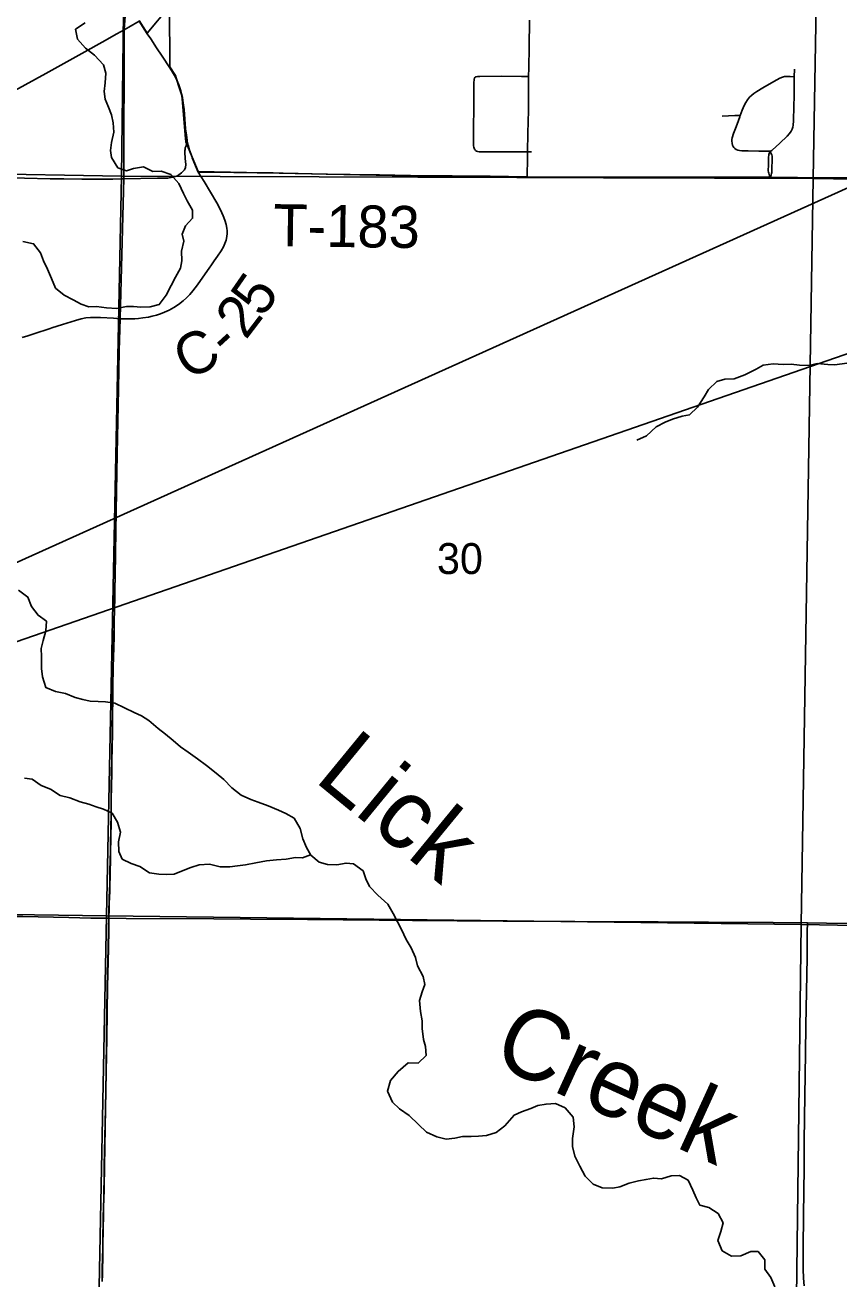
# Model space of a CAD drawing. Extents: x 0 to 34, y 0 to 22.
# Drawn here: x 5.615 to 6.718, y 15.064 to 16.761 of the extents above; entities that cross this region are included whole.
import ezdxf

# ---------------------------------------------------------------- set-up
doc = ezdxf.new("R2010")
doc.units = 0
for name, color, linetype in [('GM_X_City_Street', 7, 'Continuous'), ('GM_X_Corporation', 7, 'Continuous'), ('GM_X_County_Road', 7, 'Continuous'), ('GM_X_County_Road_Text', 7, 'Continuous'), ('GM_X_Minor_River', 7, 'Continuous'), ('GM_X_Minor_River_Text', 7, 'Continuous'), ('GM_X_Section_Text', 7, 'Continuous'), ('GM_X_State_Route', 7, 'Continuous'), ('GM_X_Township_Road', 7, 'Continuous'), ('GM_X_Township_Road_Text', 7, 'Continuous'), ('GM_X_US_Route', 7, 'Continuous'), ('SH_Data', 7, 'Continuous')]:
    doc.layers.add(name, color=color, linetype=linetype)

msp = doc.modelspace()

# ---------------------------------------------------------------- linework, layer by layer
at = {"layer": 'GM_X_City_Street'}
for points in [[(6.2953, 16.5557), (6.2955, 16.5629), (6.2958, 16.5747), (6.296, 16.5897), (6.2964, 16.6151), (6.2971, 16.6456), (6.2972, 16.6773), (6.2974, 16.6915), (6.2976, 16.7034), (6.298, 16.7314), (6.2986, 16.768)], [(6.6245, 16.5907), (6.6259, 16.5911), (6.6268, 16.5914), (6.6275, 16.5918), (6.6376, 16.6016), (6.6474, 16.6111), (6.6507, 16.6147), (6.6529, 16.6177), (6.6543, 16.6203), (6.6553, 16.623), (6.6558, 16.626), (6.6562, 16.6315), (6.6567, 16.6513), (6.657, 16.665), (6.6573, 16.6913), (6.6574, 16.7017)], [(6.2267, 16.5907), (6.2257, 16.5915), (6.2249, 16.5925), (6.2242, 16.5934), (6.2237, 16.5945), (6.2232, 16.5958), (6.2229, 16.598), (6.2226, 16.6027), (6.2227, 16.6189), (6.2233, 16.6524), (6.2232, 16.6691), (6.2233, 16.6834), (6.2236, 16.6872), (6.2237, 16.6883), (6.224, 16.6889), (6.2242, 16.6895), (6.2248, 16.6903), (6.2255, 16.691)], [(6.2255, 16.691), (6.2266, 16.6913), (6.2282, 16.6916), (6.2292, 16.6917), (6.23, 16.6917), (6.2315, 16.6918), (6.2609, 16.6922), (6.2876, 16.6917), (6.2974, 16.6915)], [(6.6245, 16.5907), (6.6167, 16.5907), (6.6092, 16.5908), (6.5948, 16.5909), (6.5861, 16.5909), (6.5832, 16.5913), (6.5809, 16.5919), (6.5787, 16.5928), (6.5768, 16.5941), (6.5752, 16.5957), (6.5743, 16.5971), (6.5736, 16.5987), (6.573, 16.601), (6.5726, 16.6045), (6.5726, 16.6062), (6.5731, 16.6086), (6.575, 16.6145), (6.5785, 16.6237), (6.5816, 16.6319), (6.5835, 16.6373), (6.5841, 16.6389), (6.5867, 16.646), (6.5894, 16.6522), (6.5917, 16.6566), (6.5941, 16.6601), (6.5967, 16.6635), (6.5997, 16.6665), (6.6025, 16.6688), (6.6066, 16.6715), (6.6147, 16.6762), (6.6297, 16.685), (6.6378, 16.6895), (6.6411, 16.6909), (6.644, 16.6916), (6.6469, 16.6918), (6.6518, 16.6916), (6.6573, 16.6913)], [(6.5598, 16.638), (6.5769, 16.6387), (6.5841, 16.6389)], [(6.2267, 16.5907), (6.2286, 16.5901), (6.2307, 16.5896), (6.2325, 16.5895), (6.2597, 16.5895), (6.2901, 16.5895), (6.296, 16.5897), (6.3013, 16.5899)], [(6.6248, 16.5547), (6.6239, 16.5572), (6.6232, 16.5591), (6.6227, 16.5609), (6.6223, 16.5624), (6.6221, 16.5641), (6.6222, 16.5719), (6.6223, 16.5811), (6.6224, 16.5829), (6.6227, 16.5847), (6.623, 16.5861), (6.6245, 16.5907)], [(6.6248, 16.5547), (6.626, 16.5585), (6.6265, 16.5602), (6.6268, 16.5616), (6.627, 16.5636), (6.6274, 16.5827), (6.6272, 16.584), (6.6267, 16.5858), (6.6261, 16.5872), (6.6245, 16.5907)]]:
    msp.add_lwpolyline(points, dxfattribs=at)
at = {"layer": 'GM_X_Corporation'}
for points in [[(5.7585, 17.5867), (6.7004, 17.5689), (6.6829, 16.5538), (5.7459, 16.557), (5.7581, 17.5537)], [(4.7439, 17.5807), (5.7581, 17.5537), (5.7459, 16.557), (4.7141, 16.575)], [(6.7004, 17.5689), (7.7016, 17.5373), (7.6999, 16.5369), (6.6829, 16.5538)], [(4.7141, 16.575), (5.7459, 16.557), (5.726, 15.5556), (4.7157, 15.5696)], [(5.7459, 16.557), (6.6829, 16.5538), (6.6666, 15.5439), (5.726, 15.5556)], [(6.6829, 16.5538), (7.6999, 16.5369), (7.6779, 15.5253), (6.6666, 15.5439)], [(4.7157, 15.5696), (5.726, 15.5556), (5.7061, 14.5519), (4.7065, 14.5692)], [(5.726, 15.5556), (6.6666, 15.5439), (6.6541, 14.5346), (6.6355, 14.5349), (5.7061, 14.5519)]]:
    msp.add_lwpolyline(points, close=True, dxfattribs=at)
for points in [[(5.7198, 15.0614), (5.72, 15.0701), (5.7201, 15.0788), (5.7203, 15.0919), (5.7206, 15.1062), (5.7207, 15.1149), (5.721, 15.1273), (5.7212, 15.136), (5.7214, 15.1478), (5.7217, 15.1615), (5.722, 15.1739), (5.7222, 15.1851), (5.7224, 15.1969), (5.7226, 15.2087), (5.7228, 15.2174), (5.7243, 15.2951), (5.7251, 15.3448), (5.726, 15.3908), (5.7269, 15.4604), (5.7281, 15.5114), (5.7285, 15.5381), (5.7288, 15.553), (5.7291, 15.566), (5.7293, 15.5735), (5.7296, 15.5809), (5.7298, 15.5896), (5.7301, 15.5989), (5.7303, 15.6083), (5.7305, 15.6176), (5.7307, 15.63), (5.731, 15.6443), (5.7313, 15.6586), (5.7315, 15.6673), (5.7317, 15.6784), (5.7319, 15.6896), (5.7319, 15.6971), (5.732, 15.7095), (5.732, 15.7176), (5.7322, 15.7269), (5.7323, 15.7325), (5.7326, 15.748), (5.7329, 15.7667), (5.7332, 15.7828), (5.7335, 15.7958), (5.7336, 15.8107), (5.7338, 15.8306), (5.734, 15.8468), (5.7342, 15.866), (5.7348, 15.8946), (5.7351, 15.9052), (5.7354, 15.9207), (5.7357, 15.9325), (5.7361, 15.9524), (5.7365, 15.9721), (5.7367, 15.9847), (5.7369, 15.9995), (5.7373, 16.0151), (5.7376, 16.0481), (5.7388, 16.104), (5.74, 16.1817), (5.7418, 16.2693), (5.7428, 16.3209), (5.7441, 16.3641), (5.7491, 16.5539), (5.7495, 16.7555), (5.7536, 16.8097)], [(5.7536, 16.8097), (5.7495, 16.7555), (5.7491, 16.5539), (5.7441, 16.3641), (5.7428, 16.3209), (5.7418, 16.2693), (5.74, 16.1817), (5.7388, 16.104), (5.7376, 16.0481), (5.7373, 16.0151), (5.7369, 15.9995), (5.7367, 15.9847), (5.7365, 15.9721), (5.7361, 15.9524), (5.7357, 15.9325), (5.7354, 15.9207), (5.7351, 15.9052), (5.7348, 15.8946), (5.7342, 15.866), (5.734, 15.8468), (5.7338, 15.8306), (5.7336, 15.8107), (5.7335, 15.7958), (5.7332, 15.7828), (5.7329, 15.7667), (5.7326, 15.748), (5.7323, 15.7325), (5.7322, 15.7269), (5.732, 15.7176), (5.732, 15.7095), (5.7319, 15.6971), (5.7319, 15.6896), (5.7317, 15.6784), (5.7315, 15.6673), (5.7313, 15.6586), (5.731, 15.6443), (5.7307, 15.63), (5.7305, 15.6176), (5.7303, 15.6083), (5.7301, 15.5989), (5.7298, 15.5896), (5.7296, 15.5809), (5.7293, 15.5735), (5.7291, 15.566), (5.7288, 15.553), (5.7285, 15.5381), (5.7281, 15.5114), (5.7269, 15.4604), (5.726, 15.3908), (5.7251, 15.3448), (5.7243, 15.2951), (5.7228, 15.2174), (5.7226, 15.2087), (5.7224, 15.1969), (5.7222, 15.1851), (5.722, 15.1739), (5.7217, 15.1615), (5.7214, 15.1478), (5.7212, 15.136), (5.721, 15.1273), (5.7207, 15.1149), (5.7206, 15.1062), (5.7203, 15.0919), (5.7201, 15.0788), (5.72, 15.0701), (5.7198, 15.0614)], [(5.7701, 16.7674), (5.7809, 16.7504), (5.811, 16.7863), (5.8114, 16.7046), (5.8192, 16.693), (5.823, 16.681), (5.8279, 16.666), (5.8287, 16.6567), (5.8324, 16.6128), (5.8332, 16.6034), (5.8419, 16.5823), (5.8501, 16.5633), (6.1563, 16.5568), (6.1872, 16.5561), (6.2206, 16.5561), (6.2673, 16.556), (6.2953, 16.556), (6.3807, 16.5555), (6.5852, 16.5555), (6.6248, 16.5554), (6.8105, 16.5532)]]:
    msp.add_lwpolyline(points, dxfattribs=at)
at = {"layer": 'GM_X_County_Road'}
msp.add_line((5.8579, 16.5496), (5.8501, 16.5624), dxfattribs=at)
for points in [[(5.7497, 16.7549), (5.756, 16.7585), (5.77, 16.7666)], [(5.7809, 16.7494), (5.7768, 16.7556), (5.7722, 16.7629), (5.77, 16.7666)], [(5.4185, 16.5607), (5.4228, 16.5647), (5.4314, 16.5719), (5.4411, 16.5796), (5.4506, 16.5865), (5.4604, 16.5931), (5.473, 16.601), (5.4923, 16.6122), (5.5216, 16.6286), (5.6017, 16.6726), (5.6436, 16.6958), (5.6963, 16.725), (5.7198, 16.738), (5.7398, 16.7492), (5.7497, 16.7549)], [(5.8114, 16.7036), (5.8013, 16.7193), (5.7937, 16.7306), (5.7859, 16.7425), (5.7809, 16.7494)], [(5.8352, 16.6041), (5.835, 16.6053), (5.8339, 16.6121), (5.8329, 16.6208), (5.8308, 16.6468), (5.8297, 16.6561), (5.8285, 16.6634), (5.8274, 16.6682), (5.8263, 16.6723), (5.8236, 16.6805), (5.8216, 16.6856), (5.8192, 16.6906), (5.8166, 16.6955), (5.8114, 16.7036)], [(5.833, 16.5725), (5.8326, 16.5768), (5.8324, 16.5806), (5.832, 16.5892), (5.832, 16.5914), (5.8322, 16.593), (5.8325, 16.5949), (5.833, 16.5971), (5.8352, 16.6041)], [(5.8501, 16.5624), (5.8442, 16.576), (5.842, 16.5816), (5.8416, 16.5825), (5.8384, 16.592), (5.8365, 16.5986), (5.8352, 16.6041)], [(5.7493, 16.5533), (5.7947, 16.554), (5.8085, 16.5539), (5.8158, 16.5552), (5.8219, 16.5572), (5.8274, 16.5612), (5.8313, 16.5652), (5.8326, 16.5686), (5.833, 16.5725)], [(5.4185, 16.5607), (5.4269, 16.5601), (5.434, 16.5598), (5.4521, 16.5591), (5.4657, 16.5587), (5.4777, 16.5583), (5.4962, 16.5578), (5.5156, 16.557), (5.5514, 16.5558), (5.5725, 16.5553), (5.5937, 16.5547), (5.6148, 16.5541), (5.6496, 16.5532), (5.6682, 16.553), (5.6924, 16.5527), (5.7136, 16.5527), (5.7344, 16.5529), (5.7459, 16.5531), (5.7477, 16.5532), (5.7493, 16.5533)], [(5.7443, 16.3635), (5.7587, 16.3637), (5.7641, 16.3639), (5.7693, 16.3642), (5.7751, 16.365), (5.7826, 16.3661), (5.7876, 16.3671), (5.7935, 16.3686), (5.7988, 16.3703), (5.8045, 16.3725), (5.8106, 16.3754), (5.8171, 16.379), (5.8232, 16.3832), (5.8296, 16.388), (5.8342, 16.392), (5.8385, 16.3964), (5.8429, 16.4015), (5.8492, 16.4099), (5.8564, 16.42), (5.865, 16.4323), (5.8682, 16.4369), (5.8717, 16.442), (5.8763, 16.4486), (5.881, 16.4558), (5.8841, 16.4612), (5.8861, 16.4656), (5.8877, 16.4702), (5.8887, 16.4749), (5.8892, 16.4792), (5.8892, 16.4828), (5.8889, 16.4864), (5.888, 16.4912), (5.8862, 16.497), (5.8837, 16.5033), (5.8801, 16.5112), (5.8752, 16.5205), (5.8668, 16.535), (5.8579, 16.5496)], [(5.7443, 16.3635), (5.7351, 16.3644), (5.7177, 16.3655), (5.7108, 16.3657), (5.7039, 16.3655), (5.6976, 16.3649), (5.6915, 16.3638), (5.6836, 16.3616), (5.6664, 16.3561), (5.6516, 16.3513), (5.6493, 16.3505), (5.6274, 16.3434), (5.6191, 16.3408), (5.6114, 16.3383)], [(5.735, 15.892), (5.735, 15.8941), (5.7353, 15.9046), (5.7356, 15.9202), (5.736, 15.932), (5.7363, 15.9518), (5.7367, 15.9716), (5.7369, 15.9842), (5.7372, 15.9989), (5.7375, 16.0145), (5.7378, 16.0475), (5.739, 16.1034), (5.7402, 16.1811), (5.7421, 16.2688), (5.743, 16.3204), (5.7443, 16.3635)], [(5.7336, 15.7913), (5.7337, 15.7953), (5.7338, 15.8102), (5.734, 15.8301), (5.7342, 15.8462), (5.7344, 15.8655), (5.735, 15.892)], [(5.729, 15.5524), (5.7294, 15.5655), (5.7296, 15.5729), (5.7298, 15.5804), (5.7301, 15.5891), (5.7303, 15.5984), (5.7306, 15.6077), (5.7308, 15.617), (5.731, 15.6294), (5.7313, 15.6437), (5.7315, 15.658), (5.7317, 15.6667), (5.7319, 15.6779), (5.7321, 15.6891), (5.7322, 15.6965), (5.7322, 15.709), (5.7323, 15.717), (5.7324, 15.7264), (5.7325, 15.732), (5.7329, 15.7475), (5.7331, 15.7661), (5.7334, 15.7823), (5.7336, 15.7913)], [(5.7201, 15.0609), (5.7202, 15.0696), (5.7204, 15.0783), (5.7206, 15.0913), (5.7208, 15.1056), (5.7209, 15.1143), (5.7212, 15.1267), (5.7214, 15.1354), (5.7216, 15.1472), (5.7219, 15.1609), (5.7222, 15.1733), (5.7224, 15.1845), (5.7226, 15.1963), (5.7229, 15.2081), (5.723, 15.2168), (5.7245, 15.2945), (5.7254, 15.3443), (5.7262, 15.3902), (5.7272, 15.4599), (5.7283, 15.5108), (5.7288, 15.5376), (5.729, 15.5524)], [(6.6707, 15.0548), (6.6699, 15.0653), (6.6694, 15.0777), (6.6692, 15.1069), (6.6697, 15.1498), (6.6702, 15.1833), (6.6706, 15.2138), (6.6708, 15.2499), (6.6713, 15.2828), (6.6724, 15.3698), (6.6731, 15.4071), (6.6745, 15.4991), (6.6749, 15.5339), (6.675, 15.5461)]]:
    msp.add_lwpolyline(points, dxfattribs=at)
at = {"layer": 'GM_X_Minor_River'}
for points in [[(5.6126, 16.4683), (5.627, 16.4653), (5.6362, 16.453), (5.6406, 16.4423), (5.646, 16.4308), (5.6511, 16.4182), (5.6565, 16.4052), (5.6685, 16.3959), (5.6805, 16.3892), (5.6914, 16.3837), (5.7019, 16.38), (5.7122, 16.3802), (5.7258, 16.3784), (5.7398, 16.3778), (5.7528, 16.3802), (5.7622, 16.3804), (5.7721, 16.3794), (5.785, 16.38), (5.7972, 16.3831), (5.8065, 16.3958), (5.8132, 16.409), (5.8191, 16.4199), (5.8262, 16.4323), (5.8279, 16.4421), (5.8274, 16.4554), (5.8303, 16.469), (5.8282, 16.4785), (5.8326, 16.4894), (5.8423, 16.4999), (5.8421, 16.5109), (5.8352, 16.5235), (5.83, 16.5335), (5.8238, 16.5469), (5.8131, 16.5589), (5.7999, 16.5637), (5.7885, 16.5631), (5.7761, 16.5694), (5.7624, 16.5671), (5.7529, 16.5638), (5.7412, 16.5682), (5.7324, 16.5821), (5.731, 16.5916), (5.7324, 16.6022), (5.7357, 16.6165), (5.7348, 16.6291), (5.7324, 16.6397), (5.7284, 16.6501), (5.724, 16.6608), (5.7227, 16.6714), (5.7241, 16.6831), (5.7247, 16.696), (5.7215, 16.7075), (5.7097, 16.7206), (5.6973, 16.73), (5.6866, 16.7423), (5.6838, 16.7556), (5.6968, 16.7641)], [(6.7285, 16.3039), (6.7121, 16.3016), (6.7027, 16.3018), (6.6883, 16.3032), (6.6776, 16.3007), (6.6643, 16.301), (6.653, 16.3023), (6.642, 16.3018), (6.6287, 16.3028), (6.6151, 16.3012), (6.6055, 16.2957), (6.5901, 16.288), (6.576, 16.2826)], [(6.576, 16.2826), (6.5631, 16.2821), (6.5524, 16.2789), (6.5412, 16.2681), (6.5353, 16.258), (6.526, 16.2441), (6.5152, 16.2337), (6.5053, 16.232), (6.4923, 16.2281), (6.4823, 16.2237), (6.4701, 16.2175), (6.4573, 16.2053), (6.444, 16.1994)], [(6.1593, 15.2628), (6.1481, 15.2733), (6.1358, 15.2853), (6.1227, 15.2946), (6.113, 15.3035), (6.1065, 15.3184), (6.1106, 15.3328), (6.1207, 15.3451), (6.1342, 15.3566), (6.1478, 15.3563), (6.1586, 15.3667), (6.1577, 15.3789), (6.1553, 15.3884), (6.1533, 15.4032), (6.1531, 15.4135), (6.1511, 15.426), (6.1498, 15.4412), (6.1535, 15.4529), (6.1571, 15.4627), (6.1546, 15.4734), (6.1469, 15.4879), (6.1441, 15.4994), (6.1383, 15.5124), (6.1317, 15.5235), (6.1255, 15.5373), (6.12, 15.5476), (6.1142, 15.5587), (6.1068, 15.5714), (6.0931, 15.5838), (6.0819, 15.5954), (6.0768, 15.6057), (6.0732, 15.6164), (6.0605, 15.6262), (6.0503, 15.6271), (6.0377, 15.6247), (6.0252, 15.625), (6.0139, 15.6282), (6.0023, 15.6379), (5.9968, 15.6483), (5.9918, 15.6597), (5.9879, 15.6739), (5.9798, 15.6877), (5.9685, 15.6943), (5.9588, 15.6987), (5.9445, 15.7047), (5.9313, 15.7095), (5.9211, 15.7131), (5.9083, 15.719), (5.8953, 15.7288), (5.8845, 15.74), (5.8744, 15.7489), (5.861, 15.759), (5.849, 15.7683), (5.8363, 15.7773), (5.8262, 15.7843), (5.8161, 15.7929), (5.8057, 15.8014), (5.7959, 15.8092), (5.7829, 15.8201), (5.7731, 15.8263), (5.7634, 15.8307), (5.7502, 15.8374), (5.7371, 15.8437), (5.7246, 15.8455), (5.7144, 15.8457), (5.7038, 15.8463), (5.6939, 15.8487), (5.6834, 15.8512), (5.6702, 15.8568), (5.6566, 15.8593), (5.6434, 15.8645), (5.6392, 15.879), (5.6379, 15.8904), (5.6378, 15.9067), (5.6373, 15.9173), (5.6401, 15.9283), (5.6438, 15.9415), (5.6444, 15.9544), (5.6332, 15.9626), (5.624, 15.9745), (5.6193, 15.9871), (5.6066, 15.9965)], [(6.0022, 15.6381), (5.9913, 15.6343), (5.9818, 15.6345), (5.9689, 15.6325), (5.9559, 15.6316), (5.9423, 15.63), (5.9282, 15.6276), (5.9141, 15.6248), (5.9031, 15.6232), (5.8928, 15.6222), (5.8799, 15.6221), (5.8652, 15.6258), (5.8512, 15.6249), (5.8401, 15.6213), (5.8298, 15.617), (5.8175, 15.6123), (5.8077, 15.6117), (5.7967, 15.6123), (5.7842, 15.6137), (5.7707, 15.6223), (5.7594, 15.6267), (5.747, 15.6326), (5.7423, 15.6426), (5.7422, 15.6559), (5.7447, 15.6691), (5.7408, 15.6824), (5.7334, 15.6947), (5.7218, 15.6999), (5.7116, 15.7031), (5.7018, 15.7067), (5.6901, 15.71), (5.6762, 15.7152), (5.663, 15.7185), (5.6499, 15.7271), (5.6375, 15.7319), (5.6251, 15.7408), (5.6149, 15.7422)], [(6.6311, 15.0534), (6.6257, 15.066), (6.6172, 15.0775), (6.6174, 15.09), (6.6082, 15.1012), (6.5983, 15.1014), (6.5849, 15.0956), (6.572, 15.0951), (6.5596, 15.1025), (6.5538, 15.1163), (6.5579, 15.1284), (6.5608, 15.1401), (6.5542, 15.1527), (6.5414, 15.1609), (6.5294, 15.1642), (6.5242, 15.1738), (6.5199, 15.1845), (6.5137, 15.1979), (6.5017, 15.2042), (6.4903, 15.2036), (6.4773, 15.1997), (6.4664, 15.2007), (6.4565, 15.199), (6.4462, 15.1969), (6.4336, 15.1937), (6.421, 15.1891), (6.4115, 15.187), (6.3971, 15.1876), (6.3847, 15.1924), (6.3739, 15.2032), (6.3669, 15.2167), (6.36, 15.2304), (6.3568, 15.2434), (6.3567, 15.2544), (6.3593, 15.2703), (6.358, 15.2832), (6.3469, 15.2959), (6.3337, 15.3015), (6.3212, 15.301), (6.3101, 15.2989), (6.3006, 15.2949), (6.2876, 15.2906), (6.2777, 15.2859), (6.2652, 15.2714), (6.2533, 15.2625), (6.2403, 15.2586), (6.2297, 15.2576), (6.2198, 15.2571), (6.2081, 15.2569), (6.1974, 15.2548), (6.186, 15.2536), (6.1732, 15.2565), (6.1593, 15.2628)]]:
    msp.add_lwpolyline(points, dxfattribs=at)
at = {"layer": 'GM_X_State_Route'}
for points in [[(4.7189, 15.5728), (4.758, 15.572), (4.7772, 15.5716), (4.8518, 15.57), (4.896, 15.5691), (4.937, 15.5682), (4.9842, 15.5672), (5.0184, 15.5664), (5.0551, 15.5656), (5.0774, 15.565), (5.1402, 15.5637), (5.193, 15.5627), (5.2235, 15.562), (5.2944, 15.5608), (5.3677, 15.5592), (5.4423, 15.558), (5.51, 15.5566), (5.5865, 15.555), (5.6126, 15.5546), (5.6747, 15.5533), (5.7046, 15.5527), (5.729, 15.5524)], [(5.729, 15.5524), (5.7524, 15.5522), (5.8712, 15.5516), (5.9209, 15.5511), (5.998, 15.5505), (6.0464, 15.5501), (6.0949, 15.5498), (6.1403, 15.5495), (6.2006, 15.5491), (6.2628, 15.5485), (6.2945, 15.5483), (6.3601, 15.5481), (6.4462, 15.5477), (6.4729, 15.5477), (6.5413, 15.5471), (6.6288, 15.5465), (6.675, 15.5461)], [(6.675, 15.5461), (6.701, 15.5459), (6.7352, 15.5455), (6.7514, 15.545), (6.7657, 15.5447), (6.7959, 15.5444), (6.8145, 15.5442), (6.8298, 15.5441)]]:
    msp.add_lwpolyline(points, dxfattribs=at)
at = {"layer": 'GM_X_Township_Road'}
for points in [[(5.8501, 16.5624), (5.873, 16.5623), (5.8984, 16.5618), (5.9298, 16.5614), (5.9515, 16.5611), (5.9649, 16.5608), (5.9854, 16.5604), (6.0234, 16.5597), (6.0557, 16.5591), (6.0955, 16.5584), (6.1377, 16.5578), (6.1738, 16.5573), (6.1937, 16.5571), (6.2453, 16.5566), (6.2953, 16.5557)], [(6.2953, 16.5557), (6.2962, 16.5557), (6.3242, 16.5554), (6.3491, 16.5551), (6.3808, 16.5548), (6.3988, 16.5547), (6.4239, 16.5546), (6.4464, 16.5544), (6.4902, 16.5546), (6.5436, 16.5547), (6.5542, 16.5548), (6.5672, 16.5548), (6.5853, 16.5547), (6.6114, 16.5547), (6.6248, 16.5547)], [(6.6248, 16.5547), (6.6387, 16.5547), (6.6598, 16.5547), (6.7003, 16.5546), (6.7394, 16.5545), (6.7833, 16.5541), (6.8106, 16.5539)]]:
    msp.add_lwpolyline(points, dxfattribs=at)
at = {"layer": 'GM_X_US_Route'}
for points in [[(4.7189, 15.5728), (4.758, 15.572), (4.7772, 15.5716), (4.8518, 15.57), (4.896, 15.5691), (4.937, 15.5682), (4.9842, 15.5672), (5.0184, 15.5664), (5.0551, 15.5656), (5.0774, 15.565), (5.1402, 15.5637), (5.193, 15.5627), (5.2235, 15.562), (5.2944, 15.5608), (5.3677, 15.5592), (5.4423, 15.558), (5.51, 15.5566), (5.5865, 15.555), (5.6126, 15.5546), (5.6747, 15.5533), (5.7046, 15.5527), (5.729, 15.5524)], [(5.729, 15.5524), (5.7524, 15.5522), (5.8712, 15.5516), (5.9209, 15.5511), (5.998, 15.5505), (6.0464, 15.5501), (6.0949, 15.5498), (6.1403, 15.5495), (6.2006, 15.5491), (6.2628, 15.5485), (6.2945, 15.5483), (6.3601, 15.5481), (6.4462, 15.5477), (6.4729, 15.5477), (6.5413, 15.5471), (6.6288, 15.5465), (6.675, 15.5461)], [(6.675, 15.5461), (6.701, 15.5459), (6.7352, 15.5455), (6.7514, 15.545), (6.7657, 15.5447), (6.7959, 15.5444), (6.8145, 15.5442), (6.8298, 15.5441)]]:
    msp.add_lwpolyline(points, dxfattribs=at)
at = {"layer": 'SH_Data'}
msp.add_lwpolyline([(4.574, 15.5703), (9.2813, 17.2011), (9.2813, 17.6911)], close=True, dxfattribs=at)

# ---------------------------------------------------------------- texts
at = {"layer": 'GM_X_County_Road_Text'}
for s, rotation, p in [('5', 55.3017, (5.9371, 16.364)), ('2', 52.6261, (5.9143, 16.3341)), ('C', 28.0518, (5.8362, 16.2796)), ('-', 42.5194, (5.8899, 16.3104))]:
    msp.add_text(s, height=0.0568, rotation=rotation, dxfattribs=at).set_placement(p)
at = {"layer": 'GM_X_Minor_River_Text'}
for s, height, rotation, p in [('Lick', 0.09474, 320.6048, (6.0054, 15.7393)), ('Creek', 0.09475, 335.4721, (6.2449, 15.3574))]:
    msp.add_text(s, height=height, rotation=rotation, dxfattribs=at).set_placement(p)
at = {"layer": 'GM_X_Section_Text'}
msp.add_text('30', height=0.04186, rotation=0, dxfattribs=at).set_placement((6.1733, 16.0183))
at = {"layer": 'GM_X_Township_Road_Text'}
msp.add_text('T-183', height=0.05682, rotation=359.1778, dxfattribs=at).set_placement((5.9513, 16.4622))

doc.saveas('drawing.dxf')
